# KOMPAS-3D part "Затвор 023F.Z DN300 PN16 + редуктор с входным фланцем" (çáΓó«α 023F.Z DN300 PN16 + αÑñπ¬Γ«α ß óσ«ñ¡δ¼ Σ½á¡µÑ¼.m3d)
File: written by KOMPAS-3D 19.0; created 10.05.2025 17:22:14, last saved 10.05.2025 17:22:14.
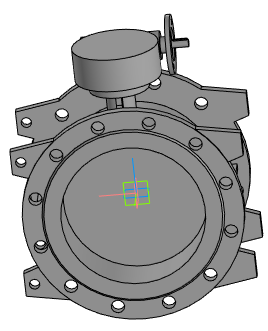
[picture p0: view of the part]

Document properties: Полное имя файла: Затвор 023F.Z DN300 PN16 + редуктор с входным фланцем.a3d

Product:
- Part/product: Затвор 023F.Z DN300 PN16 + редуктор с входным фланцем
    Масса: 101.952

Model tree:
1. Операция без истории:1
